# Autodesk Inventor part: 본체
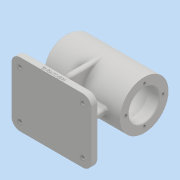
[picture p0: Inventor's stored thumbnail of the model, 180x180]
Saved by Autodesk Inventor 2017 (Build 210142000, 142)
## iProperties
Part Number: 본체
Material: 일반
Document SubType Name: Modeling
Designer: mrc
Density: 1 g/cm^3
Appearance: 기본값
Author: mrc
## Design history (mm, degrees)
sketch "스케치2"
  geometry: L1 (0, 21)-(0, 34); L2 (0, 34)-(-112, 34); L3 (-112, 34)-(-112, 0); L4 (-112, 0)-(0, 0); L5 (0, 21)-(-15, 21); L6 (-15, 21)-(-15, 24); L7 (-15, 24)-(-69, 24); L8 (-69, 24)-(-69, 21); L9 (-69, 21)-(-81, 21); L10 (-81, 21)-(-81, 17.5); L11 (-81, 17.5)-(-99, 17.5); L12 (-99, 17.5)-(-99, 16); L13 (-99, 16)-(-103, 16); L14 (-103, 16)-(-103, 10.5); L15 (-103, 10.5)-(-106, 10.5); L16 (-106, 10.5)-(-106, 0); L17 (-81, 16)-(-81, 17.5)
  constraints: 34 end point, 10 perpendicular, 3 point on line, 1 vertical
  dimensions: "d1" = 112 distance of L1.end L2.end; "d3" = 15 distance of L1.start L5.end; "d5" = 54 distance of L6.end L7.end; "d7" = 12 distance of L8.end L9.end; "d9" = 18 distance of L10.end L11.end; "d13" = 4 distance of L12.end L13.end; "d16" = 10.5 distance of L15.end L16.end; "d17" = 16 distance between parallel lines of L4 L13; "d18" = 17.5 distance between parallel lines of L4 L11; "d19" = 21 distance between parallel lines of L4 L9; "d20" = 24 distance between parallel lines of L4 L7
revolve "회전1" sketch "스케치2" stored, may be unused: angle "d21" = 90 deg
fillet "모깎기1" dims "d22" = 0.3
fillet "모깎기2" dims "d23" = 0.3
fillet "모깎기3" dims "d24" = 3
chamfer "모따기1" distance "d25" = 1; stored, may be unused: second distance "d26" = 2, angle "d27" = 45 deg
fillet "모깎기4" dims "d28" = 10
sketch "스케치3" dims "d29" = 52
  geometry: 3 further points
  constraints: 1 coincident, 1 vertical alignment, 2 other
hole "구멍1" sketch "스케치3" at (0, 26) diameter "d30" = 3.459; stored, may be unused: countersink angle "d34" = 90 deg, drill point angle "d36" = 118 deg; dims "d31" = 8, "d32" = 4, "d33" = 2, "d35" = 11
node "작업 평면1"
sketch "스케치4"
  geometry: L1 (100, -45)-(12, -45); L2 (0, -33)-(0, 33); L3 (12, 45)-(100, 45); L4 (112, 33)-(112, -33); L5 (112, -45)-(0, 45); L6 (0, -45)-(112, 45); L7 (0, 34)-(0, -34) reference; A1 r 12 centre (100, -33) between (100, -45) and (112, -33); A2 r 12 centre (100, 33) between (112, 33) and (100, 45); A3 r 12 centre (12, 33) between (12, 45) and (0, 33); A4 r 12 centre (12, -33) between (0, -33) and (12, -45); 2 further points
  constraints: 12 end point, 9 point on line, 8 point on circle, 8 tangent, 4 centre point, 3 equal radius, 2 midpoint, 2 parallel, 1 horizontal, 1 perpendicular
  dimensions: "d41" = 112 distance of L5.end L6.end; "d42" = 90 distance of L6.start L5.end; "d43" = 12 radius of A1
extrude "돌출1" join sketch "스케치4" distance "d44" = 10; taper "d45" = 0 deg
sketch "스케치5"
  geometry: L1 (-94, -4)-(-18, -4); L2 (-18, -4)-(-18, 4); L3 (-18, 4)-(-94, 4); L4 (-94, 4)-(-94, -4); L5 (-94, -4)-(-18, 4); L6 (-18, -4)-(-94, 4); L7 (-112, 33)-(-112, -33) reference; L8 (-60, 34)-(-52, 34); L9 (-52, 34)-(-52, -34); L10 (-52, -34)-(-60, -34); L11 (-60, -34)-(-60, 34); L12 (-60, 34)-(-52, -34); L13 (-52, 34)-(-60, -34); L14 (-100, -45)-(-12, -45) reference; 2 further points
  constraints: 24 end point, 4 midpoint, 4 parallel, 2 horizontal, 2 perpendicular
  dimensions: "d46" = 76 distance of L3.end L2.end; "d47" = 8 distance of L2.end L1.end; "d48" = 56 distance from line of L7 point (-56, 0); "d49" = 8 distance of L9.end L10.end; "d50" = 68 distance of L8.end L9.end; "d51" = 49 distance between parallel lines of L14 L3
extrude "돌출2" join sketch "스케치5" stored distance "d52" = 10; taper "d53" = 0 deg
sketch "스케치6"
  geometry: A1 r 12 centre (-100, 33) between (-100, 45) and (-112, 33) reference; A2 r 12 centre (-12, 33) between (0, 33) and (-12, 45) reference; 3 further points
  constraints: 2 coincident
hole "구멍2" sketch "스케치6" at (-100, 33), (-12, 33) diameter "d54" = 5.5; stored, may be unused: countersink angle "d58" = 90 deg, drill point angle "d60" = 0 deg; dims "d55" = 8, "d56" = 9.5, "d57" = 5.4, "d59" = 10
fillet "모깎기5" dims "d61" = 3
fillet "모깎기6" dims "d62" = 3
fillet "모깎기7" dims "d63" = 3
fillet "모깎기8" dims "d64" = 3
fillet "모깎기9" dims "d65" = 3
fillet "모깎기10" dims "d66" = 3
fillet "모깎기11" dims "d67" = 3
sketch "스케치7"
  geometry: L1 (-12, 0)-(-12, 7) reference; L2 (0, 0)-(88, 0) reference; L3 (100, 0)-(100, 7) reference; 2 further points
  constraints: 1 other
  dimensions: "d69" = 3 distance from line of L2 point (44, 3); "d72" = 56 distance from line of point (44, 3) L3
feature "엠보싱1" sketch "스케치7" dims "d70" = 0.5, "d71" = 0
node "솔리드1"
pattern_circular "원형 패턴1" dims angle "d38" = 360 deg
mirror "미러1"
other parameters: "d10" = 90 deg (derived), "d40" = -74
